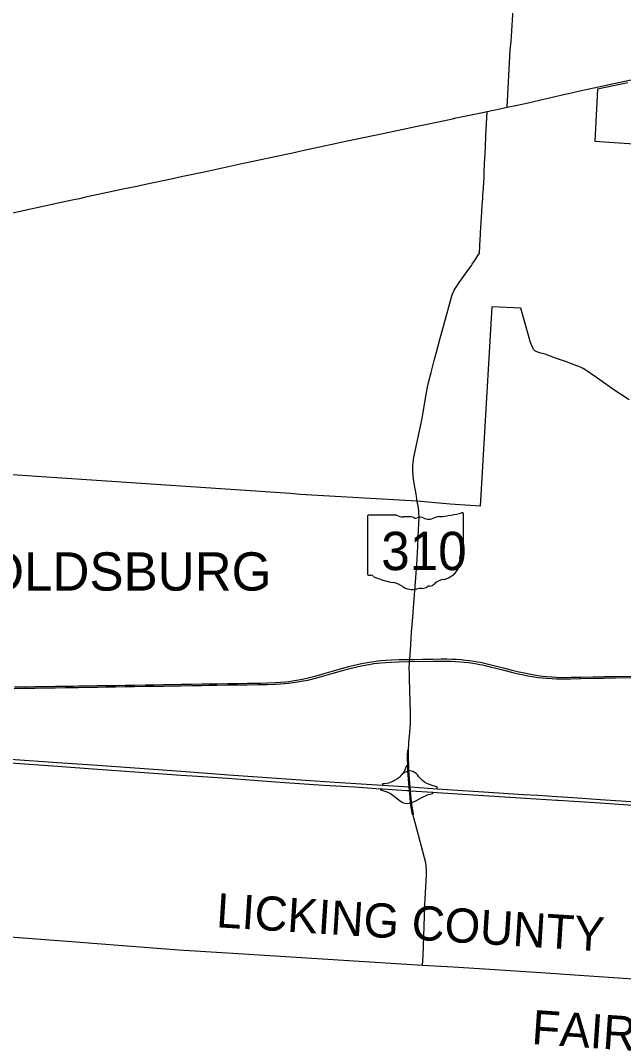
# Model space of a CAD drawing. Extents: x 1853412 to 2125412, y 679418 to 855418.
# Drawn here: x 1905911 to 1923564, y 702363 to 732306 of the extents above; entities that cross this region are included whole.
import ezdxf

# ---------------------------------------------------------------- set-up
doc = ezdxf.new("R2010")
doc.units = 0
for name, color, linetype in [('GM_X_Corporation', 7, 'Continuous'), ('GM_X_Corporation_Text', 7, 'Continuous'), ('GM_X_County', 7, 'Continuous'), ('GM_X_County_Text', 7, 'Continuous'), ('GM_X_Interchange_Ramps', 7, 'Continuous'), ('GM_X_State_Location', 7, 'Continuous'), ('GM_X_State_Route', 7, 'Continuous'), ('GM_X_State_Shield', 7, 'Continuous'), ('GM_X_US_Route', 7, 'Continuous'), ('UT_P_Electric', 7, 'Continuous')]:
    doc.layers.add(name, color=color, linetype=linetype)

msp = doc.modelspace()

# ---------------------------------------------------------------- linework, layer by layer
at = {"layer": 'GM_X_Corporation'}
for points in [[(1923686, 730478), (1922806, 730294), (1922720, 728778), (1923433, 728722), (1924175, 728675)], [(1923728, 721198), (1923283, 721494), (1922777, 721852), (1922463, 722068), (1922385, 722115), (1922340, 722141), (1922304, 722159), (1922115, 722227), (1921891, 722316), (1921573, 722425), (1921274, 722538), (1921148, 722569), (1921058, 722599), (1921003, 722617), (1920971, 722635), (1920949, 722655), (1920933, 722673), (1920844, 722881), (1920556, 723883), (1919706, 723920), (1919365, 718089), (1918485, 718152), (1917525, 718232), (1914097, 718433), (1913810, 718462), (1910748, 718668), (1904355, 719098)]]:
    msp.add_lwpolyline(points, dxfattribs=at)
at = {"layer": 'GM_X_County'}
msp.add_lwpolyline([(1926703, 704052), (1922414, 704344), (1921285, 704420), (1920102, 704498), (1918575, 704596), (1917683, 704648), (1913213, 704931), (1912287, 704990), (1910548, 705097), (1908910, 705222), (1907401, 705337), (1903803, 705612)], dxfattribs=at)
at = {"layer": 'GM_X_Interchange_Ramps'}
msp.add_lwpolyline([(1917280, 710342), (1917254, 710330), (1917213, 710315), (1917174, 710301), (1917142, 710288), (1917121, 710278), (1917112, 710283)], dxfattribs=at)
at = {"layer": 'GM_X_State_Route'}
for p, q in [((1917283, 711181), (1917306, 711452)), ((1917265, 710967), (1917279, 711127)), ((1917428, 708971), (1917408, 709042)), ((1917568, 708450), (1917566, 708460))]:
    msp.add_line(p, q, dxfattribs=at)
for points in [[(1920154, 729766), (1920249, 731440), (1920275, 731693), (1920341, 732783)], [(1919496, 728136), (1919506, 728235), (1919520, 728603), (1919535, 728933), (1919574, 729644)], [(1919453, 727268), (1919461, 727419), (1919481, 727714), (1919480, 727892), (1919490, 728072), (1919496, 728136)], [(1919397, 726413), (1919403, 726544), (1919417, 726705), (1919428, 726888), (1919442, 727093), (1919443, 727109)], [(1919443, 727109), (1919450, 727218), (1919453, 727268)], [(1919369, 725916), (1919377, 726020), (1919382, 726138), (1919388, 726216), (1919397, 726413)], [(1919207, 725279), (1919302, 725426), (1919346, 725495), (1919353, 725709), (1919369, 725916)], [(1919132, 725170), (1919200, 725268), (1919207, 725279)], [(1917501, 718383), (1917491, 718445), (1917428, 718817), (1917410, 718975), (1917397, 719123), (1917398, 719247), (1917403, 719356), (1917419, 719462), (1917445, 719610), (1917671, 720660), (1917749, 721134), (1917820, 721520), (1917856, 721707), (1917929, 722006), (1918023, 722355), (1918103, 722636), (1918196, 723007), (1918329, 723497), (1918419, 723815), (1918540, 724251), (1918606, 724408), (1918662, 724504), (1918749, 724636), (1919011, 724990), (1919110, 725138), (1919132, 725170)], [(1917384, 714729), (1917428, 715245), (1917510, 716384), (1917540, 716910), (1917553, 717190), (1917575, 717580), (1917584, 717745), (1917577, 717929), (1917560, 718054), (1917526, 718229), (1917501, 718383)], [(1917362, 714407), (1917375, 714622), (1917384, 714729)], [(1917325, 713870), (1917338, 714052), (1917362, 714407)], [(1917302, 713540), (1917309, 713604), (1917316, 713747), (1917325, 713870)], [(1917296, 713208), (1917294, 713313), (1917302, 713540)], [(1917316, 712479), (1917311, 712589), (1917308, 712780), (1917302, 712946), (1917296, 713208)], [(1917306, 711452), (1917307, 711463), (1917325, 711747), (1917333, 711993), (1917333, 712020), (1917320, 712386), (1917316, 712479)], [(1917279, 711127), (1917280, 711143), (1917283, 711181)], [(1917332, 709404), (1917316, 709578), (1917300, 709764), (1917291, 709874), (1917254, 710330), (1917249, 710488), (1917241, 710732), (1917245, 710816), (1917251, 710921), (1917255, 710948), (1917265, 710967)], [(1917342, 709622), (1917332, 709762), (1917321, 709872), (1917280, 710342), (1917275, 710488), (1917270, 710731), (1917270, 710810), (1917274, 710900), (1917272, 710948), (1917265, 710967)], [(1917408, 709042), (1917390, 709066), (1917373, 709118), (1917354, 709223), (1917344, 709287), (1917332, 709404)], [(1917361, 709416), (1917346, 709576), (1917342, 709622)], [(1917408, 709042), (1917412, 709074), (1917408, 709132), (1917388, 709238), (1917369, 709366), (1917361, 709416)], [(1917566, 708460), (1917513, 708648), (1917428, 708971)], [(1917725, 705792), (1917745, 706424), (1917797, 707299), (1917797, 707469), (1917775, 707653), (1917577, 708419), (1917568, 708450)], [(1917684, 704645), (1917698, 704926), (1917725, 705792)]]:
    msp.add_lwpolyline(points, dxfattribs=at)
at = {"layer": 'GM_X_State_Shield'}
for p, q in [((1916073, 717800), (1916073, 716099)), ((1916921, 717830), (1916100, 717830)), ((1918875, 716982), (1918875, 717872)), ((1918874, 716982), (1918875, 716982))]:
    msp.add_line(p, q, dxfattribs=at)
for centre, major_axis, start_param, end_param in [((1916105, 717804), (32.5, 0), 1.712693, 3.28349), ((1917116, 718027), (315, 0), 4.042523, 4.731795), ((1917221, 716875), (1130, 0), 1.404758, 1.657858), ((1917477, 717813), (90.8, 0), 3.836095, 5.185415), ((1917611, 717616), (189, 0), 0.950623, 2.079405), ((1917854, 717886), (227, 0), 4.081561, 5.145723), ((1918256, 717310), (598, 0), 1.699011, 2.107814), ((1917877, 720149), (2971, 0), 4.814394, 5.042369), ((1918843, 717875), (31.2, 0), 6.141152, 7.989035), ((1918867, 716917), (48.3, 0), 1.883978, 3.671073), ((1918560, 716804), (290, 0), 5.934695, 6.695948), ((1918841, 716978), (33.4, 0), 5.05454, 6.418171), ((1918043, 716496), (743, 0), 5.101752, 6.440018), ((1918986, 716609), (211, 0), 2.387724, 3.262537), ((1916105, 716095), (32.7, 0), 3.00124, 4.508301), ((1916110, 716269), (250, 0), 4.665946, 4.897461), ((1916161, 716001), (90.1, 0), 0.519207, 1.627899), ((1917299, 717529), (2146, 0), 4.195997, 4.488961), ((1918356, 715622), (407, 0), 1.647645, 2.488434), ((1916659, 715335), (671, 0), 0.823519, 1.323587), ((1917385, 715993), (426, 0), 4.026481, 4.996735), ((1917631, 715404), (350, 0), 1.495662, 1.94098), ((1917663, 715865), (227, 0), 4.691044, 5.507374), ((1917868, 715700), (63.9, 0), 1.147584, 2.315152), ((1917841, 715934), (240, 0), 4.937069, 5.64225)]:
    msp.add_ellipse(centre, major_axis=major_axis, ratio=0.8, start_param=start_param, end_param=end_param, dxfattribs=at)
at = {"layer": 'GM_X_US_Route'}
for p, q in [((1921713, 713037), (1921820, 713036)), ((1921820, 713036), (1921926, 713037))]:
    msp.add_line(p, q, dxfattribs=at)
for points in [[(1912935, 712914), (1913143, 712918), (1913380, 712926), (1913523, 712936), (1913666, 712950), (1913764, 712962), (1913875, 712976), (1913989, 712995), (1914159, 713026), (1914296, 713056), (1914449, 713091), (1914568, 713124), (1914804, 713191), (1915071, 713269), (1915380, 713359), (1915523, 713399), (1915643, 713429), (1915765, 713458), (1915893, 713486), (1916011, 713508), (1916118, 713525), (1916263, 713546), (1916378, 713561), (1916463, 713570), (1916605, 713583), (1916776, 713593), (1916995, 713599), (1917195, 713603), (1917309, 713604)], [(1917302, 713540), (1917991, 713554), (1918198, 713557), (1918364, 713557), (1918511, 713555), (1918640, 713549), (1918798, 713536), (1918899, 713527), (1919032, 713511), (1919154, 713493), (1919269, 713475), (1919351, 713459), (1919437, 713442), (1919549, 713419), (1919665, 713391), (1919822, 713353), (1920017, 713302), (1920284, 713235), (1920476, 713186), (1920640, 713150), (1920762, 713127)], [(1917309, 713604), (1917442, 713607), (1917681, 713611), (1917989, 713617), (1918222, 713621), (1918390, 713621), (1918540, 713617), (1918666, 713610), (1918823, 713598), (1918936, 713585), (1919057, 713571), (1919178, 713554), (1919294, 713535), (1919375, 713520), (1919455, 713503), (1919571, 713478), (1919691, 713450), (1919847, 713411), (1920043, 713361), (1920309, 713294), (1920502, 713245), (1920661, 713208), (1920788, 713181), (1920955, 713152), (1921070, 713134), (1921189, 713119), (1921319, 713105), (1921475, 713092), (1921610, 713084), (1921822, 713078)], [(1914326, 713002), (1914548, 713054), (1914796, 713124), (1915064, 713201), (1915374, 713291), (1915515, 713331), (1915636, 713362), (1915757, 713391), (1915885, 713422), (1916110, 713461), (1916255, 713482), (1916371, 713497), (1916456, 713506), (1916593, 713519), (1916775, 713529), (1916987, 713535), (1917302, 713540)], [(1912937, 712872), (1913133, 712874), (1913376, 712881), (1913520, 712889), (1913761, 712910), (1913897, 712927), (1914019, 712946), (1914190, 712975), (1914326, 713002)], [(1920762, 713127), (1920952, 713096), (1921067, 713080), (1921187, 713066), (1921313, 713055), (1921473, 713043), (1921601, 713038), (1921713, 713037)], [(1921822, 713078), (1922018, 713081), (1922315, 713087), (1922676, 713094), (1922998, 713101), (1923316, 713106), (1924359, 713126)], [(1921926, 713037), (1922022, 713039), (1922316, 713045), (1922677, 713052), (1922999, 713058), (1923317, 713064), (1924360, 713084)], [(1905726, 712755), (1906051, 712761), (1906330, 712765), (1906640, 712770), (1906931, 712776), (1907231, 712781), (1907460, 712784), (1907600, 712786), (1907858, 712790), (1908178, 712796), (1908418, 712800), (1908697, 712804), (1908976, 712809), (1909254, 712813), (1909567, 712819), (1909693, 712821), (1909826, 712823), (1910098, 712827), (1910349, 712831), (1910617, 712836), (1910925, 712840), (1911213, 712845), (1911437, 712850)], [(1905734, 712798), (1905927, 712801), (1906055, 712803), (1906338, 712808), (1906648, 712813), (1906939, 712818), (1907239, 712824), (1907468, 712827), (1907609, 712828), (1907850, 712832), (1908169, 712838), (1908412, 712842), (1908692, 712846), (1908973, 712850), (1909254, 712855), (1909570, 712860), (1909693, 712863), (1909818, 712865), (1910097, 712869), (1910340, 712873), (1910616, 712878), (1910936, 712883), (1911217, 712888), (1911432, 712891), (1911658, 712895), (1911977, 712899), (1912260, 712904), (1912544, 712909), (1912862, 712913), (1912935, 712914)], [(1911437, 712850), (1911655, 712852), (1911975, 712857), (1912254, 712861), (1912551, 712866), (1912855, 712870), (1912937, 712872)]]:
    msp.add_lwpolyline(points, dxfattribs=at)
at = {"layer": 'UT_P_Electric'}
for p, q in [((1921851, 730147), (1921954, 730170)), ((1920154, 729766), (1920206, 729777)), ((1920206, 729777), (1920413, 729821)), ((1921054, 709629), (1921618, 709592))]:
    msp.add_line(p, q, dxfattribs=at)
for points in [[(1922833, 730363), (1924238, 730665), (1925065, 730849), (1925929, 731048), (1927740, 731467), (1928042, 731536), (1928250, 731584), (1928672, 731682), (1929104, 731786), (1929340, 731842), (1929365, 731849)], [(1921954, 730170), (1922280, 730244), (1922833, 730363)], [(1920413, 729821), (1920776, 729899), (1921437, 730054), (1921851, 730147)], [(1919574, 729644), (1919942, 729723), (1920154, 729766)], [(1915292, 728741), (1916565, 729011), (1917527, 729214), (1918147, 729339), (1918554, 729430)], [(1918554, 729430), (1918656, 729453), (1918709, 729462), (1918962, 729515), (1919247, 729576), (1919574, 729644)], [(1912678, 728181), (1913403, 728338), (1913836, 728426), (1914255, 728516), (1914667, 728607), (1915120, 728704), (1915292, 728741)], [(1910661, 727744), (1911336, 727885), (1912388, 728118), (1912678, 728181)], [(1909575, 727513), (1910319, 727673), (1910661, 727744)], [(1907648, 727100), (1907716, 727116), (1907866, 727152), (1908642, 727317)], [(1908642, 727317), (1908952, 727383), (1909321, 727459), (1909575, 727513)], [(1901957, 725878), (1902458, 725978), (1903032, 726099), (1903686, 726245), (1904240, 726364), (1905813, 726704), (1907014, 726966), (1907380, 727042), (1907580, 727085), (1907648, 727100)], [(1900292, 710841), (1900488, 710864), (1900763, 710881), (1901124, 710886), (1901417, 710877), (1902079, 710829), (1902917, 710765), (1903996, 710690), (1905616, 710577), (1906997, 710477), (1908167, 710395), (1909393, 710308), (1910617, 710222), (1911089, 710188), (1911973, 710126), (1913517, 710014), (1914784, 709928), (1915690, 709872), (1916454, 709820), (1916505, 709817), (1917219, 709770)], [(1905618, 710687), (1906999, 710588), (1908169, 710506), (1909395, 710419), (1910619, 710332), (1911124, 710293), (1912007, 710228), (1913551, 710117), (1914818, 710030), (1915724, 709975), (1916510, 709920), (1917291, 709874), (1917321, 709872), (1918107, 709817), (1919464, 709729), (1920634, 709656), (1921054, 709629)], [(1917249, 710488), (1917209, 710489), (1917183, 710422), (1917138, 710325), (1917112, 710283), (1917079, 710238), (1917049, 710203), (1917015, 710168), (1916976, 710133), (1916931, 710100), (1916864, 710059), (1916811, 710031), (1916759, 710009), (1916686, 709987), (1916628, 709976), (1916571, 709965), (1916512, 709964), (1916510, 709920)], [(1918107, 709817), (1918109, 709872), (1918056, 709884), (1917958, 709911), (1917882, 709940), (1917807, 709976), (1917742, 710015), (1917682, 710063), (1917576, 710172), (1917530, 710223), (1917491, 710264), (1917447, 710298), (1917398, 710321), (1917351, 710334), (1917296, 710344), (1917280, 710342)], [(1916454, 709820), (1916452, 709792), (1916523, 709772), (1916575, 709751), (1916663, 709720), (1916739, 709682), (1916809, 709636), (1916860, 709596)], [(1917219, 709770), (1917300, 709764), (1917332, 709762), (1917983, 709718), (1918104, 709712), (1919461, 709624), (1921002, 709526)], [(1917361, 709416), (1917373, 709420), (1917461, 709459), (1917697, 709580), (1917764, 709608), (1917845, 709647), (1917909, 709664), (1917981, 709678), (1917983, 709718)], [(1916860, 709596), (1916995, 709488), (1917064, 709433), (1917127, 709410), (1917177, 709396), (1917235, 709392), (1917301, 709397), (1917332, 709404), (1917361, 709416)], [(1921002, 709526), (1921611, 709487), (1921653, 709484)], [(1921618, 709592), (1922079, 709562), (1922891, 709509), (1923921, 709441)], [(1921653, 709484), (1922876, 709405), (1923976, 709334), (1924953, 709272), (1926212, 709198), (1927022, 709147), (1927583, 709115), (1928179, 709079), (1929037, 709028), (1930543, 708941), (1931495, 708883), (1932092, 708846), (1932411, 708827), (1932923, 708794), (1934110, 708727), (1935111, 708666), (1935585, 708637), (1936315, 708593), (1936732, 708577), (1936955, 708577)]]:
    msp.add_lwpolyline(points, dxfattribs=at)

# ---------------------------------------------------------------- texts
at = {"layer": 'GM_X_Corporation_Text'}
msp.add_text('REYNOLDSBURG', height=1120, rotation=0, dxfattribs=at).set_placement((1900690, 715619))
at = {"layer": 'GM_X_County_Text'}
for s, rotation, p in [('LICKING COUNTY', 356.3996, (1911626, 705769)), ('FAIRFIELD COUNTY', 356.1646, (1920857, 702350))]:
    msp.add_text(s, height=1000, rotation=rotation, dxfattribs=at).set_placement(p)
at = {"layer": 'GM_X_State_Location'}
for s in ['s', 'r']:
    msp.add_text(s, height=1, dxfattribs=at).set_placement((1917429, 717189))
msp.add_text('310', height=1, rotation=0, dxfattribs=at).set_placement((1917076, 717116))
at = {"layer": 'GM_X_State_Shield'}
msp.add_text('310', height=1120.7, dxfattribs=at).set_placement((1916472, 716219))

doc.saveas('drawing.dxf')
